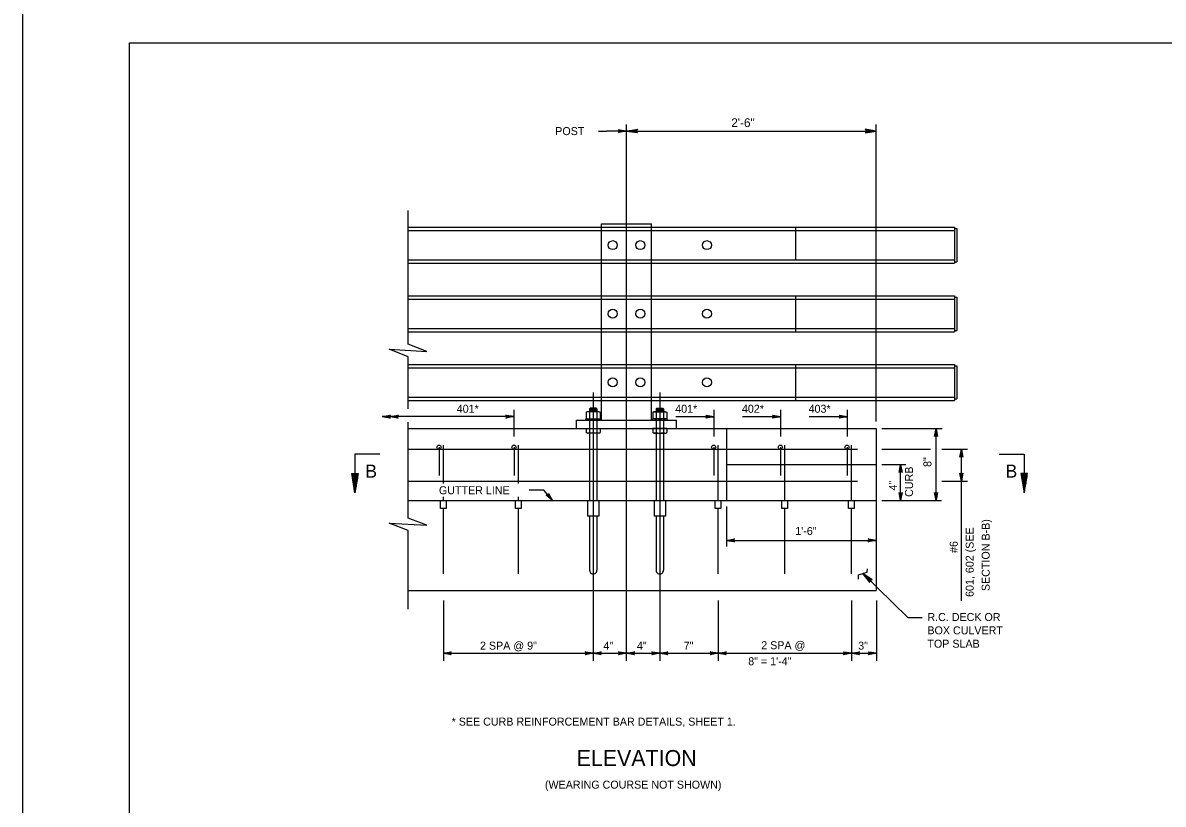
# Model space of a CAD drawing. Extents: x 641054 to 641910, y 298137 to 299325.
# Drawn here: x 641054.5 to 641482.1, y 298430.9 to 298723.9 of the extents above; entities that cross this region are included whole.
import ezdxf

# ---------------------------------------------------------------- set-up
doc = ezdxf.new("R2010")
doc.units = 0
for name, color, linetype in [('1', 7, 'Continuous'), ('2', 7, 'Continuous'), ('BRDG_BORDER', 7, 'Continuous'), ('Default', 7, 'Continuous'), ('PLT-BNDY', 7, 'Continuous'), ('S-DETL-DIMS', 7, 'Continuous'), ('S-DETL-T120', 7, 'Continuous'), ('S-WALL-RBAR', 7, 'Continuous')]:
    doc.layers.add(name, color=color, linetype=linetype)

# ---------------------------------------------------------------- blocks, each defined once
blk = doc.blocks.new('LT')
at = {"layer": 'BRDG_BORDER'}
blk.add_lwpolyline([(0, 0), (-11.184875, -2.097125), (-10.323, -1.5), (-9.878625, -0.75), (-9.75, 0), (-9.878625, 0.75), (-10.323, 1.5), (-11.184875, 2.097125), (0, 0), (-10.323, 1.5), (-9.878625, 0.75), (0, 0), (-9.75, 0), (-9.878625, -0.75), (0, 0), (-10.323, -1.5)], dxfattribs=at)

msp = doc.modelspace()

# ---------------------------------------------------------------- linework, layer by layer
at = {"layer": '1'}
for p, q in [((641267.02, 298578.42), (641267.02, 298544.76)), ((641269.75, 298578.42), (641269.75, 298544.76)), ((641291.99, 298578.42), (641291.99, 298544.76)), ((641294.72, 298578.42), (641294.72, 298544.76)), ((641267.02, 298538.86), (641267.02, 298518.61)), ((641269.75, 298538.86), (641269.75, 298518.61)), ((641291.99, 298538.86), (641291.99, 298518.61)), ((641294.72, 298538.86), (641294.72, 298518.61)), ((641369.5, 298517.37), (641386.4, 298500.87)), ((641386.4, 298500.87), (641391.69, 298500.87))]:
    msp.add_line(p, q, dxfattribs=at)
for centre, start, end in [((641268.38, 298518.61), 179.9999, 0), ((641293.35, 298518.61), 180, 0.0001)]:
    msp.add_arc(centre, 1.37, start, end, dxfattribs=at)
at = {"layer": '2'}
for p, q in [((641094.49, 298152.38), (641094.49, 298716.38)), ((641094.49, 298716.38), (641880.49, 298716.38)), ((641271.5, 298647.27), (641271.5, 298648.53)), ((641271.5, 298648.53), (641290.23, 298648.53)), ((641290.23, 298647.27), (641290.23, 298648.53)), ((641198.93, 298647.27), (641403.85, 298647.27)), ((641198.93, 298646), (641403.85, 298646)), ((641271.5, 298633.77), (641271.5, 298647.27)), ((641290.23, 298633.77), (641290.23, 298647.27)), ((641344.23, 298647.27), (641344.23, 298635.01)), ((641403.85, 298647.27), (641403.85, 298633.77)), ((641403.85, 298646.72), (641404.72, 298646.72)), ((641404.72, 298646.72), (641404.72, 298634.29)), ((641198.93, 298635.01), (641403.85, 298635.01)), ((641198.93, 298633.77), (641403.85, 298633.77)), ((641271.5, 298621.53), (641271.5, 298633.77)), ((641290.23, 298621.53), (641290.23, 298633.77)), ((641403.85, 298634.29), (641404.72, 298634.29)), ((641198.93, 298621.53), (641403.85, 298621.53)), ((641198.93, 298620.26), (641403.85, 298620.26)), ((641271.5, 298608.03), (641271.5, 298621.53)), ((641290.23, 298608.03), (641290.23, 298621.53)), ((641344.23, 298621.53), (641344.23, 298608.03)), ((641403.85, 298621.53), (641403.85, 298608.03)), ((641403.85, 298620.98), (641404.72, 298620.98)), ((641404.72, 298620.98), (641404.72, 298608.55)), ((641198.93, 298609.3), (641403.85, 298609.3)), ((641198.93, 298608.03), (641403.85, 298608.03)), ((641271.5, 298595.8), (641271.5, 298608.03)), ((641290.23, 298595.8), (641290.23, 298608.03)), ((641403.85, 298608.55), (641404.72, 298608.55)), ((641198.93, 298595.8), (641403.85, 298595.8)), ((641198.93, 298594.53), (641403.85, 298594.53)), ((641271.5, 298582.3), (641271.5, 298595.8)), ((641290.23, 298582.3), (641290.23, 298595.8)), ((641344.23, 298595.8), (641344.23, 298582.3)), ((641403.85, 298595.8), (641403.85, 298582.3)), ((641403.85, 298595.8), (641403.85, 298582.28)), ((641403.85, 298595.25), (641404.72, 298595.25)), ((641404.72, 298595.25), (641404.72, 298582.82)), ((641198.93, 298583.54), (641403.85, 298583.54)), ((641198.93, 298582.28), (641403.85, 298582.28)), ((641271.5, 298574.88), (641271.5, 298582.28)), ((641290.23, 298574.88), (641290.23, 298582.28)), ((641403.85, 298582.82), (641404.72, 298582.82)), ((641266.11, 298578.03), (641265.76, 298577.83)), ((641265.76, 298577.83), (641265.76, 298575.55)), ((641266.11, 298575.35), (641265.76, 298575.55)), ((641270.66, 298578.03), (641266.11, 298578.03)), ((641267.02, 298579.17), (641267.25, 298579.4)), ((641267.02, 298579.17), (641267.02, 298578.03)), ((641269.75, 298579.17), (641267.02, 298579.17)), ((641269.75, 298578.49), (641267.02, 298578.49)), ((641267.02, 298577.83), (641267.02, 298575.55)), ((641269.53, 298578.83), (641267.24, 298578.83)), ((641269.53, 298578.15), (641267.24, 298578.15)), ((641269.52, 298579.4), (641267.25, 298579.4)), ((641269.75, 298579.17), (641269.52, 298579.4)), ((641269.75, 298579.17), (641269.75, 298578.03)), ((641269.75, 298577.84), (641269.75, 298575.54)), ((641270.66, 298578.03), (641271.01, 298577.83)), ((641270.66, 298575.35), (641271.01, 298575.55)), ((641271.01, 298577.83), (641271.01, 298575.55)), ((641291.08, 298578.03), (641290.72, 298577.83)), ((641290.72, 298577.83), (641290.72, 298575.55)), ((641291.08, 298575.35), (641290.72, 298575.55)), ((641291.08, 298578.03), (641295.63, 298578.03)), ((641291.99, 298579.17), (641292.21, 298579.4)), ((641291.99, 298579.17), (641291.99, 298578.03)), ((641291.99, 298579.17), (641294.72, 298579.17)), ((641291.99, 298578.49), (641294.72, 298578.49)), ((641291.99, 298577.84), (641291.99, 298575.54)), ((641292.21, 298579.4), (641294.49, 298579.4)), ((641292.21, 298578.83), (641294.5, 298578.83)), ((641292.21, 298578.15), (641294.5, 298578.15)), ((641294.72, 298579.17), (641294.49, 298579.4)), ((641294.72, 298579.17), (641294.72, 298578.03)), ((641294.72, 298577.83), (641294.72, 298575.55)), ((641295.63, 298578.03), (641295.98, 298577.83)), ((641295.63, 298575.35), (641295.98, 298575.55)), ((641295.98, 298577.83), (641295.98, 298575.55)), ((641198.93, 298571.76), (641374.51, 298571.76)), ((641262.14, 298574.88), (641299.6, 298574.88)), ((641262.14, 298571.76), (641262.14, 298574.88)), ((641265.76, 298571.76), (641265.76, 298570.26)), ((641265.76, 298571.76), (641271.01, 298571.76)), ((641267.02, 298571.76), (641267.02, 298570.26)), ((641269.75, 298571.76), (641269.75, 298570.26)), ((641271.01, 298571.76), (641271.01, 298570.26)), ((641290.72, 298571.76), (641290.72, 298570.26)), ((641295.98, 298571.76), (641290.72, 298571.76)), ((641291.99, 298571.76), (641291.99, 298570.26)), ((641294.72, 298571.76), (641294.72, 298570.26)), ((641295.98, 298571.76), (641295.98, 298570.26)), ((641299.6, 298571.76), (641299.6, 298574.88)), ((641318.33, 298571.76), (641318.33, 298544.76)), ((641374.51, 298571.76), (641374.51, 298511)), ((641266.11, 298570.05), (641265.76, 298570.26)), ((641270.66, 298570.05), (641266.11, 298570.05)), ((641270.66, 298570.05), (641271.01, 298570.26)), ((641291.08, 298570.05), (641290.72, 298570.26)), ((641291.08, 298570.05), (641295.63, 298570.05)), ((641295.63, 298570.05), (641295.98, 298570.26)), ((641318.33, 298558.26), (641374.51, 298558.26)), ((641177.83, 298554.89), (641180.27, 298554.89)), ((641179.05, 298547.57), (641177.83, 298554.89)), ((641177.83, 298554.89), (641177.83, 298554.89)), ((641177.88, 298554.89), (641177.88, 298554.6)), ((641177.97, 298554.89), (641177.97, 298554.01)), ((641178.07, 298554.89), (641178.07, 298553.43)), ((641178.17, 298554.89), (641178.17, 298552.84)), ((641178.27, 298554.89), (641178.27, 298552.26)), ((641178.36, 298554.89), (641178.36, 298551.67)), ((641178.46, 298554.89), (641178.46, 298551.09)), ((641178.56, 298554.89), (641178.56, 298550.5)), ((641178.66, 298554.89), (641178.66, 298549.91)), ((641178.75, 298554.89), (641178.75, 298549.33)), ((641178.85, 298554.89), (641178.85, 298548.74)), ((641178.95, 298554.89), (641178.95, 298548.16)), ((641180.27, 298554.89), (641179.05, 298547.57)), ((641179.05, 298554.89), (641179.05, 298547.57)), ((641179.15, 298554.89), (641179.15, 298548.16)), ((641179.24, 298554.89), (641179.24, 298548.74)), ((641179.34, 298554.89), (641179.34, 298549.33)), ((641179.44, 298554.89), (641179.44, 298549.91)), ((641179.54, 298554.89), (641179.54, 298550.5)), ((641179.63, 298554.89), (641179.63, 298551.09)), ((641179.73, 298554.89), (641179.73, 298551.67)), ((641179.83, 298554.89), (641179.83, 298552.26)), ((641179.93, 298554.89), (641179.93, 298552.84)), ((641180.02, 298554.89), (641180.02, 298553.43)), ((641180.12, 298554.89), (641180.12, 298554.01)), ((641180.22, 298554.89), (641180.22, 298554.6)), ((641431.18, 298554.89), (641428.74, 298554.89)), ((641428.74, 298554.89), (641429.96, 298547.57)), ((641428.79, 298554.89), (641428.79, 298554.6)), ((641428.89, 298554.89), (641428.89, 298554.01)), ((641428.98, 298554.89), (641428.98, 298553.43)), ((641429.08, 298554.89), (641429.08, 298552.84)), ((641429.18, 298554.89), (641429.18, 298552.26)), ((641429.28, 298554.89), (641429.28, 298551.67)), ((641429.37, 298554.89), (641429.37, 298551.09)), ((641429.47, 298554.89), (641429.47, 298550.5)), ((641429.57, 298554.89), (641429.57, 298549.91)), ((641429.67, 298554.89), (641429.67, 298549.33)), ((641429.77, 298554.89), (641429.77, 298548.74)), ((641429.86, 298554.89), (641429.86, 298548.16)), ((641429.96, 298547.57), (641431.18, 298554.89)), ((641429.96, 298554.89), (641429.96, 298547.57)), ((641430.06, 298554.89), (641430.06, 298548.16)), ((641430.16, 298554.89), (641430.16, 298548.74)), ((641430.25, 298554.89), (641430.25, 298549.33)), ((641430.35, 298554.89), (641430.35, 298549.91)), ((641430.45, 298554.89), (641430.45, 298550.5)), ((641430.55, 298554.89), (641430.55, 298551.09)), ((641430.64, 298554.89), (641430.64, 298551.67)), ((641430.74, 298554.89), (641430.74, 298552.26)), ((641430.84, 298554.89), (641430.84, 298552.84)), ((641430.94, 298554.89), (641430.94, 298553.43)), ((641431.03, 298554.89), (641431.03, 298554.01)), ((641431.13, 298554.89), (641431.13, 298554.6)), ((641431.18, 298554.89), (641431.18, 298554.89)), ((641198.93, 298544.76), (641374.51, 298544.76)), ((641266.26, 298544.76), (641266.26, 298538.86)), ((641270.44, 298544.76), (641270.44, 298538.86)), ((641291.24, 298544.76), (641291.24, 298538.86)), ((641295.42, 298544.76), (641295.42, 298538.86)), ((641270.44, 298538.86), (641266.26, 298538.86)), ((641295.42, 298538.86), (641291.24, 298538.86)), ((641198.93, 298511), (641374.51, 298511))]:
    msp.add_line(p, q, dxfattribs=at)
for points in [[(641284.84, 298682.78), (641284.69, 298683.06), (641280.87, 298683.27), (641284.84, 298682.78), (641285.04, 298682.6), (641280.87, 298683.27), (641284.69, 298683.46), (641284.83, 298683.75), (641280.87, 298683.27), (641285.04, 298683.94), (641284.83, 298683.75)], [(641370.54, 298682.78), (641370.69, 298683.06), (641374.51, 298683.27), (641370.54, 298682.78), (641370.33, 298682.6), (641374.51, 298683.27), (641370.69, 298683.46), (641370.55, 298683.75), (641374.51, 298683.27), (641370.33, 298683.94), (641370.55, 298683.75)], [(641188.38, 298562.17), (641179.05, 298562.17), (641179.05, 298547.57)], [(641420.63, 298562.17), (641429.96, 298562.17), (641429.96, 298547.57)], [(641367.82, 298515.29), (641367.83, 298516.86), (641371.14, 298517.85), (641371.26, 298519.08)], [(641372.69, 298514.95), (641372.38, 298514.85), (641369.5, 298517.37), (641372.69, 298514.95), (641372.96, 298514.94), (641369.5, 298517.37), (641372.1, 298514.57), (641372, 298514.27), (641369.5, 298517.37), (641372.02, 298513.98), (641372, 298514.27)]]:
    msp.add_lwpolyline(points, dxfattribs=at)
for points in [[(641265.65, 298574.88), (641265.65, 298575.35), (641271.11, 298575.35), (641271.11, 298574.88)], [(641296.08, 298574.88), (641296.08, 298575.35), (641290.62, 298575.35), (641290.62, 298574.88)]]:
    msp.add_lwpolyline(points, close=True, dxfattribs=at)
for centre in [(641275.72, 298640.5), (641286.02, 298640.5), (641311, 298640.5), (641275.72, 298614.78), (641286.02, 298614.78), (641311, 298614.78), (641275.72, 298589.03), (641286.02, 298589.03), (641311, 298589.03)]:
    msp.add_circle(centre, 1.69, dxfattribs=at)
for centre, radius, start, end in [((641266.39, 298576.95), 1.08, 54.2983, 90.0007), ((641266.39, 298576.43), 1.08, 270.0017, 305.7041), ((641268.38, 298573.34), 4.69, 73.0665, 106.9347), ((641268.38, 298580.04), 4.69, 253.0683, 286.9366), ((641270.38, 298576.95), 1.08, 90.0001, 125.7026), ((641270.38, 298576.43), 1.08, 234.299, 270.0015), ((641291.36, 298576.95), 1.08, 54.2974, 89.9999), ((641291.36, 298576.43), 1.08, 269.9985, 305.701), ((641293.35, 298573.34), 4.69, 73.0653, 106.9335), ((641293.35, 298580.04), 4.69, 253.0634, 286.9317), ((641295.35, 298576.95), 1.08, 89.9993, 125.7017), ((641295.35, 298576.43), 1.08, 234.2959, 269.9983), ((641266.39, 298571.13), 1.08, 270.0017, 305.7041), ((641268.38, 298574.74), 4.69, 253.0683, 286.9366), ((641270.38, 298571.14), 1.08, 234.299, 270.0015), ((641291.36, 298571.14), 1.08, 269.9985, 305.701), ((641293.35, 298574.74), 4.69, 253.0634, 286.9317), ((641295.35, 298571.13), 1.08, 234.2959, 269.9983)]:
    msp.add_arc(centre, radius, start, end, dxfattribs=at)
at = {"layer": 'Default'}
for p, q in [((641280.87, 298484.59), (641280.87, 298685.75)), ((641280.87, 298683.27), (641374.51, 298683.27)), ((641268.38, 298585.21), (641268.38, 298484.59)), ((641293.36, 298585.21), (641293.36, 298484.59)), ((641212.22, 298507.27), (641212.22, 298484.6)), ((641315.22, 298507.25), (641315.22, 298484.59)), ((641365.18, 298507.25), (641365.18, 298484.59)), ((641374.55, 298507.25), (641374.55, 298484.59)), ((641212.22, 298487.47), (641374.55, 298487.47))]:
    msp.add_line(p, q, dxfattribs=at)
at = {"layer": 'PLT-BNDY'}
msp.add_lwpolyline([(641054.49, 298731.38), (641895.49, 298731.38), (641895.49, 298137.38), (641054.49, 298137.38)], close=True, dxfattribs=at)
at = {"layer": 'S-DETL-DIMS'}
for p, q in [((641270.4, 298683.27), (641273.4, 298683.27)), ((641280.87, 298683.27), (641273.4, 298683.27)), ((641374.51, 298574.39), (641374.51, 298685.75)), ((641198.93, 298603.32), (641198.93, 298653.52)), ((641198.93, 298579.1), (641198.93, 298598.64)), ((641238.67, 298576.19), (641189.24, 298576.19)), ((641238.67, 298578.8), (641238.67, 298568.76)), ((641313.55, 298576.18), (641299.34, 298576.18)), ((641313.55, 298578.79), (641313.55, 298568.75)), ((641338.56, 298576.18), (641324.34, 298576.18)), ((641338.56, 298578.79), (641338.56, 298568.75)), ((641363.56, 298576.18), (641349.35, 298576.18)), ((641363.56, 298578.79), (641363.56, 298568.75)), ((641198.93, 298538.12), (641198.93, 298574.06)), ((641376.6, 298571.76), (641399.18, 298571.76)), ((641396.93, 298544.76), (641396.93, 298571.76)), ((641376.6, 298563.96), (641394.82, 298563.96)), ((641399.08, 298563.96), (641408.69, 298563.96)), ((641406.44, 298507.17), (641406.44, 298563.96)), ((641376.6, 298558.26), (641385.54, 298558.26)), ((641383.65, 298544.76), (641383.65, 298558.26)), ((641399.08, 298552.05), (641408.69, 298552.05)), ((641249.8, 298548.66), (641244.4, 298548.66)), ((641253.05, 298544.76), (641249.8, 298548.66)), ((641318.33, 298542.51), (641318.33, 298527.54)), ((641376.6, 298544.76), (641398.95, 298544.76)), ((641318.33, 298540.2), (641318.33, 298528.14)), ((641198.93, 298503.99), (641198.93, 298533.44)), ((641318.33, 298529.79), (641374.51, 298529.79))]:
    msp.add_line(p, q, dxfattribs=at)
for points in [[(641198.93, 298598.64), (641191.9, 298601.49), (641205.96, 298600.64), (641198.93, 298603.32)], [(641198.93, 298533.44), (641191.9, 298536.29), (641205.96, 298535.44), (641198.93, 298538.12)]]:
    msp.add_lwpolyline(points, dxfattribs=at)
at = {"layer": 'S-WALL-RBAR'}
for p, q in [((641198.93, 298563.96), (641367.44, 298563.96)), ((641210.56, 298564.75), (641210.56, 298554.15)), ((641212.14, 298565.53), (641212.14, 298551.1)), ((641238.68, 298564.75), (641238.68, 298554.15)), ((641240.26, 298565.53), (641240.26, 298551.1)), ((641313.55, 298564.74), (641313.55, 298554.14)), ((641315.13, 298565.52), (641315.13, 298544.78)), ((641338.56, 298564.74), (641338.56, 298554.14)), ((641340.14, 298565.52), (641340.14, 298544.78)), ((641363.56, 298564.74), (641363.56, 298554.14)), ((641365.15, 298565.52), (641365.15, 298544.78)), ((641198.93, 298552.05), (641367.44, 298552.05)), ((641212.14, 298546.16), (641212.14, 298544.8)), ((641240.26, 298546.16), (641240.26, 298544.8)), ((641211.09, 298541.8), (641211.09, 298544.8)), ((641213.19, 298541.8), (641211.09, 298541.8)), ((641212.14, 298541.8), (641212.14, 298517.25)), ((641213.19, 298544.8), (641213.19, 298541.8)), ((641239.21, 298541.8), (641239.21, 298544.8)), ((641241.31, 298541.8), (641239.21, 298541.8)), ((641240.26, 298541.8), (641240.26, 298517.25)), ((641241.31, 298544.8), (641241.31, 298541.8)), ((641314.09, 298541.79), (641314.09, 298544.78)), ((641316.18, 298541.79), (641314.09, 298541.79)), ((641315.13, 298541.79), (641315.13, 298517.24)), ((641316.18, 298544.78), (641316.18, 298541.79)), ((641339.09, 298541.79), (641339.09, 298544.78)), ((641341.19, 298541.79), (641339.09, 298541.79)), ((641340.14, 298541.79), (641340.14, 298517.24)), ((641341.19, 298544.78), (641341.19, 298541.79)), ((641364.1, 298541.79), (641364.1, 298544.78)), ((641366.2, 298541.79), (641364.1, 298541.79)), ((641365.15, 298541.79), (641365.15, 298517.24)), ((641366.2, 298544.78), (641366.2, 298541.79))]:
    msp.add_line(p, q, dxfattribs=at)
for centre in [(641210.56, 298564.75), (641238.68, 298564.75), (641313.55, 298564.74), (641338.56, 298564.74), (641363.56, 298564.74)]:
    msp.add_circle(centre, 0.782, dxfattribs=at)

# ---------------------------------------------------------------- block references
at = {"layer": 'S-DETL-DIMS', "xscale": 0.2683336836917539, "yscale": 0.26833868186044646}
for p in [(641280.87, 298683.27), (641238.67, 298576.19), (641313.55, 298576.18), (641338.56, 298576.18), (641363.56, 298576.18), (641374.51, 298529.79), (641268.38, 298487.47), (641280.87, 298487.47), (641293.36, 298487.47), (641315.22, 298487.47), (641365.18, 298487.47), (641374.55, 298487.47)]:
    msp.add_blockref('LT', p, dxfattribs=at)
at = {"layer": 'S-DETL-DIMS'}
for p, xscale, yscale, rotation in [((641189.24, 298576.19), 0.26819958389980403, 0.26820457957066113, 180), ((641192.25, 298576.19), 0.26819958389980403, 0.26820457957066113, 180), ((641396.93, 298571.76), 0.2683336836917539, 0.26833868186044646, 90), ((641406.44, 298563.96), 0.2683336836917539, 0.26833868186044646, 90), ((641383.65, 298558.26), 0.2683336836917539, 0.26833868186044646, 90), ((641406.44, 298552.05), 0.2683336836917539, 0.26833868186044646, -90), ((641253.05, 298544.76), 0.268333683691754, 0.26833868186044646, -50.27635144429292), ((641383.65, 298544.76), 0.2683336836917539, 0.26833868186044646, -90), ((641396.93, 298544.76), 0.2683336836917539, 0.26833868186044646, -90), ((641318.33, 298529.79), 0.2683336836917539, 0.26833868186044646, 180), ((641212.14, 298487.47), 0.2683336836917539, 0.26833868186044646, 180), ((641268.38, 298487.47), 0.2683336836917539, 0.26833868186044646, 180), ((641280.87, 298487.47), 0.2683336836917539, 0.26833868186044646, 180), ((641293.36, 298487.47), 0.2683336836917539, 0.26833868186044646, 180), ((641315.22, 298487.47), 0.2683336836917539, 0.26833868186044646, 180), ((641365.18, 298487.47), 0.2683336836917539, 0.26833868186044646, 180)]:
    msp.add_blockref('LT', p, dxfattribs=dict(at, xscale=xscale, yscale=yscale, rotation=rotation))

# ---------------------------------------------------------------- texts
at = {"layer": '2'}
for s, height, p in [('2\'-6"', 3.3, (641320.15, 298684.78)), ('B', 4.88, (641182.95, 298553.33)), ('B', 4.88, (641423.02, 298553.33)), ('R.C. DECK OR', 3.0001, (641393.69, 298499.55)), ('BOX CULVERT', 3.0001, (641393.69, 298494.55)), ('2 SPA @', 3, (641331.38, 298488.97)), ('TOP SLAB', 3, (641393.69, 298489.55)), ('8" = 1\'-4"', 3, (641326.51, 298482.97)), ('ELEVATION', 6, (641262.14, 298445.17))]:
    msp.add_text(s, height=height, dxfattribs=at).set_placement(p)
at = {"layer": 'S-DETL-DIMS'}
for s, height, p in [('  POST', 3.001, (641251.91, 298681.77)), ('GUTTER LINE', 3.0014, (641210.52, 298547.08)), ('1\'-6"', 3.001, (641344.14, 298531.81)), ('2 SPA @ 9"', 3.001, (641225.92, 298488.81)), ('4"', 3.001, (641272.21, 298488.81)), ('4"', 3.001, (641284.76, 298488.81)), ('7"', 3.001, (641302.3, 298488.81)), ('3"', 3.001, (641367.74, 298488.81))]:
    msp.add_text(s, height=height, dxfattribs=at).set_placement(p)
for s, height, p in [('8"', 3.001, (641395.21, 298557.33)), ('CURB', 3.001, (641388.28, 298546.11)), ('4"', 3.001, (641382.28, 298548.49)), ('SECTION B-B)', 3.0013, (641417.05, 298510.77)), ('601, 602 (SEE', 3.0013, (641411.04, 298508.58)), ('#6', 3.001, (641405.04, 298525.08))]:
    msp.add_text(s, height=height, rotation=90, dxfattribs=at).set_placement(p)
at = {"layer": 'S-DETL-T120'}
for s, height, p in [('401*', 3.002, (641217.21, 298577.66)), ('401*', 3.002, (641299.12, 298577.65)), ('402*', 3.002, (641324.13, 298577.65)), ('403*', 3.002, (641349.14, 298577.65)), ('* SEE CURB REINFORCEMENT BAR DETAILS, SHEET 1.', 3, (641215.28, 298460.33)), ('(WEARING COURSE NOT SHOWN)', 3, (641250.27, 298436.7))]:
    msp.add_text(s, height=height, dxfattribs=at).set_placement(p)

doc.saveas('drawing.dxf')
